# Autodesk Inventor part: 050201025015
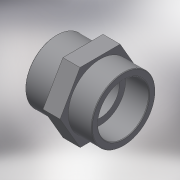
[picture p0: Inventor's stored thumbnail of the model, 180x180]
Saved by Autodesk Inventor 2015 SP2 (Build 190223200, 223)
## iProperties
Created: 2017-10
Part Number: 050201025015
Material: Generic
Description: PLASSON THREADED REDUCER PVC 2.1/2"-1.1/2"F
Document SubType Name: Modeling
Designer: KIM
Density: 1 g/cm^3
Appearance: Default
Author: KIM
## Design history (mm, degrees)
derived "050201.ipt"
feature "Solid1::050201.ipt"
tag "TaggingFeature1"
body "Solid1"
other parameters: "d0" = 66, "d1" = 44.845, "d4" = 35.876, "d5" = 29, "d6" = 22, "d8" = 75.184, "d10" = 22, "d13" = 0, "d14" = 0.75184, "d16" = 60.1472, "d17" = 62.783, "R_" = 75.184, "lt_" = 22, "H_" = 66, "G_" = 44.845, "lt_1" = 29
